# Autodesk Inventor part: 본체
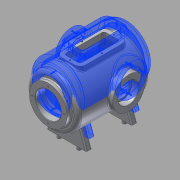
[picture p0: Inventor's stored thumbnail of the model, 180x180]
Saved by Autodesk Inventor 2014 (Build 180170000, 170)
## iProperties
Created: 2016-02
Part Number: 본체
Material: 알루미늄 6061
Document SubType Name: Modeling
Designer: mduedu
Density: 2.71 g/cm^3
Appearance: 알루미늄 - 평지
Mass: 2844 g
Surface Area: 2031.16 cm^2
Volume: 1049.45 cm^3
Author: mduedu
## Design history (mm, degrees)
sketch "스케치2"
  geometry: L1 (0, 100)-(0, -100); L2 (65, -75.993)-(65, 100); L3 (65, 100)-(0, 100); A1 r 100 centre (0, 0) between (0, -100) and (65, -75.993); 2 further points
  constraints: 6 end point, 2 midpoint, 2 point on circle, 1 centre point, 1 coincident, 1 horizontal, 1 parallel, 1 vertical
  dimensions: "d3" = 200 distance of L1.start L1.end; "d5" = 130 diameter of L2 L1; "d6" = 100 radius of A1
revolve "회전1" sketch "스케치2" stored, may be unused: angle "d7" = 90 deg
sketch "스케치3"
  geometry: C1 r 47.5 at (0, 0); 1 further point
  constraints: 1 centre point, 1 coincident
  dimensions: "d8" = 95 diameter of C1
extrude "돌출2" join sketch "스케치3" distance "d10" = 10; taper "d11" = 0 deg
sketch "스케치5"
  geometry: L1 (47.5, 110)-(47.5, 100) reference; L2 (47.5, 100)-(65, 100) reference; L3 (65, 100)-(65, -75.993) reference; L4 (-65, -75.993)-(-65, 100) reference; L5 (-65, 100)-(-47.5, 100) reference; L6 (-47.5, 100)-(-47.5, 110) reference; L7 (-47.5, 110)-(47.5, 110) reference; L8 (55, 85)-(55, -71.239); L9 (0, 85)-(55, 85); L10 (0, 85)-(0, -90); A1 r 100 centre (0, 0) between (0, -100) and (65, -75.993) reference; A2 r 100 centre (0, 0) between (-65, -75.993) and (0, -100) reference; A3 r 90 centre (0, 0) between (0, -90) and (55, -71.239); 1 further point
  constraints: 6 end point, 2 point on circle, 1 centre point, 1 parallel, 1 perpendicular, 1 point on line, 1 vertical
  dimensions: "d13" = 10 distance between parallel lines of L3 L8; "d14" = 10 radial gap between concentric circles of A3 A1; "d15" = 15 distance between parallel lines of L9 L2
revolve "회전2" sketch "스케치5" stored, may be unused: angle "d16" = 90 deg
hole "구멍1" diameter "d19" = 65; stored, may be unused: countersink angle "d23" = 90 deg, drill point angle "d25" = 118 deg; dims "d17" = 10, "d18" = 10, "d20" = 6, "d21" = 4, "d22" = 2, "d24" = 8
node "작업 평면1"
sketch "스케치6"
  geometry: L1 (47.5, 110)-(-47.5, 110) reference; C1 r 40 at (0, -17); 1 further point
  constraints: 1 centre point, 1 vertical alignment
  dimensions: "d27" = 80 diameter of C1; "d29" = 127 distance from line of C1.centre L1
extrude "돌출3" join sketch "스케치6" stored distance "d30" = 10; taper "d31" = 0 deg
hole "구멍2" diameter "d34" = 42; stored, may be unused: countersink angle "d38" = 90 deg, drill point angle "d40" = 118 deg; dims "d32" = 10, "d33" = 10, "d35" = 6, "d36" = 52, "d37" = 18, "d39" = 8
sketch "스케치7" dims "d41" = 65
  geometry: C1 r 40 at (0, 0) reference; 3 further points
  constraints: 2 vertical alignment, 1 coincident, 2 other
hole "구멍3" sketch "스케치7" at (0, 32.5) diameter "d43" = 3.242; stored, may be unused: countersink angle "d47" = 90 deg, drill point angle "d49" = 118 deg; dims "d44" = 11, "d45" = 13, "d46" = 18, "d48" = 13
sketch "스케치8" dims "d53" = 80
  geometry: 3 further points
  constraints: 2 vertical alignment, 1 coincident, 2 other
hole "구멍4" sketch "스케치8" at (0, 40) diameter "d56" = 3.242; stored, may be unused: countersink angle "d60" = 90 deg, drill point angle "d62" = 118 deg; dims "d57" = 11, "d58" = 13, "d59" = 18, "d61" = 13
fillet "모깎기1" dims "d66" = 10
fillet "모깎기2" dims "d67" = 3
fillet "모깎기3" dims "d68" = 0.3
chamfer "모따기1" distance "d69" = 1; stored, may be unused: second distance "d70" = 2, angle "d71" = 45 deg
node "작업 평면5"
sketch "스케치10"
  geometry: L1 (-50, -64)-(50, -64); L2 (50, -64)-(50, -50); L3 (50, -50)-(-50, -50); L4 (-50, -50)-(-50, -64); L5 (-50, 0)-(50, 0); L6 (-50, 64)-(50, 64); L7 (50, 64)-(50, 50); L8 (50, 50)-(-50, 50); L9 (-50, 50)-(-50, 64); 2 further points
  constraints: 18 end point, 4 symmetric about line, 2 parallel, 2 perpendicular, 1 coincident, 1 horizontal, 1 midpoint
  dimensions: "d80" = 14 distance of L3.end L1.start; "d82" = 100 distance of L1.start L1.end; "d130" = 50 horizontal distance of L3.end point (0, 0); "d131" = 50 horizontal distance of L3.end point (0, 0); "d132" = 100 distance of L5.start L5.end
extrude "돌출5" join sketch "스케치10" stored distance "d84" = 10; taper "d85" = 0 deg
feature "면 기울기3" dims angle "d135" = 20 deg
sketch "스케치11"
  geometry: L1 (-85, -50)-(-85, 50); L2 (-65, 90)-(-65, -71.239) reference; L3 (-100, -50)-(-41.533, -50) reference; L4 (-100, 50)-(-41.533, 50) reference; 1 further point
  constraints: 2 end point, 2 point on line
  dimensions: "d87" = 20 distance between parallel lines of L1 L2
feature "리브1" sketch "스케치11" dims "d88" = 1, "d89" = 8, "d90" = 0, "d91" = 0, "d92" = 1, "d93" = 1
fillet "모깎기5" dims "d103" = 3
fillet "모깎기6" dims "d105" = 3
node "작업 평면6"
sketch "스케치15"
  geometry: L1 (-30, 60)-(30, 60); L2 (30, 60)-(30, -60); L3 (30, -60)-(-30, -60); L4 (-30, -60)-(-30, 60); 2 further points
  constraints: 8 end point, 2 parallel, 1 horizontal, 1 midpoint, 1 perpendicular, 1 vertical alignment
  dimensions: "d110" = 60 distance of L2.end L3.end; "d112" = 60 distance from line of L3 point (0, 0); "d113" = 120 distance of L1.end L2.end
extrude "돌출8" join sketch "스케치15" stored distance "d114" = 10; taper "d115" = 0 deg
fillet "모깎기7" dims "d116" = 15
sketch "스케치16"
  geometry: L1 (-30, -45)-(-30, 45) reference; L2 (30, 45)-(30, -45) reference; L3 (-15, 60)-(15, 60) reference; L4 (15, -60)-(-15, -60) reference; L5 (-20, -45)-(-20, 45); L6 (-15, 50)-(15, 50); L7 (20, 45)-(20, -45); L8 (15, -50)-(-15, -50); A1 r 15 centre (-15, -45) between (-30, -45) and (-15, -60) reference; A2 r 15 centre (-15, 45) between (-15, 60) and (-30, 45) reference; A3 r 15 centre (15, 45) between (30, 45) and (15, 60) reference; A4 r 15 centre (15, -45) between (15, -60) and (30, -45) reference; A5 r 5 centre (-15, -45) between (-20, -45) and (-15, -50); A6 r 5 centre (-15, 45) between (-15, 50) and (-20, 45); A7 r 5 centre (15, 45) between (20, 45) and (15, 50); A8 r 5 centre (15, -45) between (15, -50) and (20, -45)
  constraints: 8 end point, 8 point on circle, 4 centre point, 7 other
  dimensions: "d137" = 10 distance between parallel lines of L5 L1
extrude "돌출9" cut sketch "스케치16" stored distance "d118" = 10; taper "d119" = 0 deg
fillet "모깎기8" dims "d120" = 3
sketch "스케치17"
  geometry: L1 (-30, -45)-(-30, 45) reference; L2 (30, 45)-(30, -45) reference; L3 (-20, 45)-(-20, -45) reference; L4 (-15, -50)-(15, -50) reference; L5 (20, -45)-(20, 45) reference; L6 (15, 50)-(-15, 50) reference; L7 (-15, 60)-(15, 60) reference; L8 (15, -60)-(-15, -60) reference; L9 (15, 55)-(-15, 55); L10 (-25, 45)-(-25, -45); L11 (-15, -55)-(15, -55); L12 (25, -45)-(25, 45); A1 r 5 centre (-15, 45) between (-15, 50) and (-20, 45) reference; A2 r 5 centre (-15, -45) between (-20, -45) and (-15, -50) reference; A3 r 5 centre (15, -45) between (15, -50) and (20, -45) reference; A4 r 5 centre (15, 45) between (20, 45) and (15, 50) reference; A5 r 15 centre (-15, 45) between (-15, 60) and (-30, 45) reference; A6 r 15 centre (15, 45) between (30, 45) and (15, 60) reference; A7 r 15 centre (15, -45) between (15, -60) and (30, -45) reference; A8 r 15 centre (-15, -45) between (-30, -45) and (-15, -60) reference; A9 r 10 centre (-15, 45) between (-15, 55) and (-25, 45); A10 r 10 centre (-15, -45) between (-25, -45) and (-15, -55); A11 r 10 centre (15, -45) between (15, -55) and (25, -45); A12 r 10 centre (15, 45) between (25, 45) and (15, 55); 4 further points
  constraints: 8 end point, 8 point on circle, 4 centre point, 4 midpoint, 7 other
  dimensions: "d138" = 5 distance between parallel lines of L9 L7
hole "구멍5" sketch "스케치17" at (0, 55), (25, 0), (0, -55), (-25, 0) diameter "d122" = 3.242; stored, may be unused: countersink angle "d126" = 90 deg, drill point angle "d128" = 118 deg; dims "d123" = 9, "d124" = 13, "d125" = 18, "d127" = 11
fillet "모깎기9" dims "d129" = 3
sketch "스케치18"
  geometry: L1 (-46.807, 50)-(46.807, 50) reference; L2 (50, 53)-(50, 61) reference; L3 (46.807, 64)-(-46.807, 64) reference; L4 (-50, 61)-(-50, 53) reference; L5 (-50, 57)-(50, 57); L6 (0, 64)-(0, 50); C1 r 5 at (-25, 57); C2 r 5 at (25, 57); 5 further points; 4 other entities
  constraints: 4 end point, 4 midpoint, 2 centre point, 1 point on line, 1 symmetric about line, 5 other
  dimensions: "d139" = 10 diameter of C1; "d141" = 25 distance from line of L6 C1.centre; "d147" = 57 vertical distance of C2.centre point (0, 0) (derived)
extrude "돌출10" join sketch "스케치18" distance "d142" = 10; taper "d143" = 0 deg
chamfer "모따기2" distance "d144" = 1; stored, may be unused: second distance "d145" = 2, angle "d146" = 45 deg
node "작업 평면7"
fillet "모깎기10" dims "d148" = 0.5
node "솔리드2"
pattern_circular "원형 패턴1" dims angle "d51" = 360 deg
mirror "대칭1"
pattern_circular "원형 패턴2" dims angle "d64" = 360 deg
mirror "대칭2"
node "투영된 루프1"
node "절단 모서리 투영1"
node "절단 모서리 투영2"
node "절단 모서리 투영3"
other parameters: "d26" = 75
